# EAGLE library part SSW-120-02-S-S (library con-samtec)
THROUGH-HOLE .025" SQ POST SOCKET Source: Samtec SSW.pdf
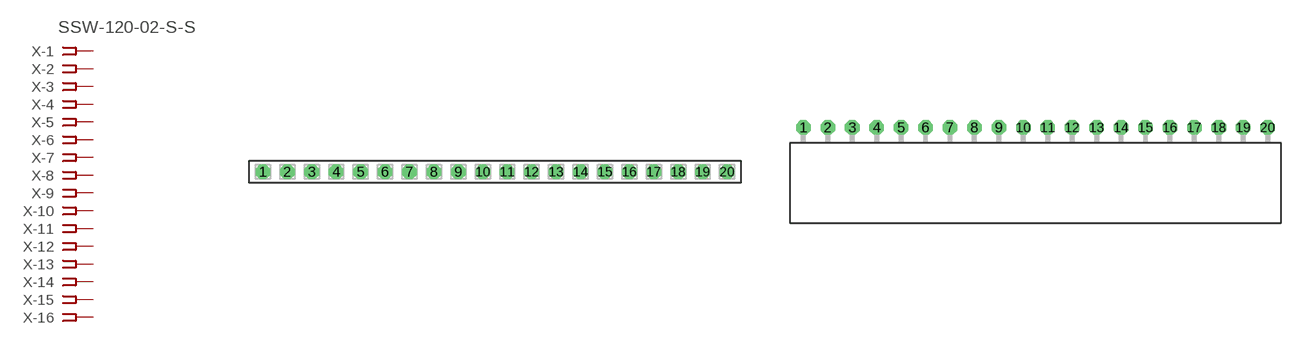
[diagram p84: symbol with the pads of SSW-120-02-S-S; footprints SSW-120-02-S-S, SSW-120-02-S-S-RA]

Designator prefix X; gates -1=FPINV -2=FPIN -3=FPIN -4=FPIN -5=FPIN -6=FPIN -7=FPIN -8=FPIN -9=FPIN -10=FPIN -11=FPIN -12=FPIN -13=FPIN -14=FPIN -15=FPIN -16=FPIN -17=FPIN -18=FPIN -19=FPIN -20=FPIN

## SSW-120-02-S-S (MPN: SSW-120-02-S-S; OC_FARNELL: unknown; OC_NEWARK: 11P9641)  [SSW-120-02-S-S]
1  -1:1  pas
2  -2:1  pas
3  -3:1  pas
4  -4:1  pas
5  -5:1  pas
6  -6:1  pas
7  -7:1  pas
8  -8:1  pas
9  -9:1  pas
10  -10:1  pas
11  -11:1  pas
12  -12:1  pas
13  -13:1  pas
14  -14:1  pas
15  -15:1  pas
16  -16:1  pas
17  -17:1  pas
18  -18:1  pas
19  -19:1  pas
20  -20:1  pas

## SSW-120-02-S-S-RA (MPN: SSW-120-02-S-S-RA; OC_FARNELL: unknown; OC_NEWARK: 11P9642)  [SSW-120-02-S-S-RA]
Pads as for SSW-120-02-S-S

## Footprint SSW-120-02-S-S (pad centres in mm)
THROUGH-HOLE .025" SQ POST SOCKET Source: Samtec SSW.pdf
drill 1 pad 1.5 octagon: 1 -24.13,0; 2 -21.59,0; 3 -19.05,0; 4 -16.51,0; 5 -13.97,0; 6 -11.43,0; 7 -8.89,0; 8 -6.35,0; 9 -3.81,0; 10 -1.27,0; 11 1.27,0; 12 3.81,0; 13 6.35,0; 14 8.89,0; 15 11.43,0; 16 13.97,0; 17 16.51,0; 18 19.05,0; 19 21.59,0; 20 24.13,0

## Footprint SSW-120-02-S-S-RA (pad centres in mm)
THROUGH-HOLE .025" SQ POST SOCKET Source: Samtec SSW.pdf
drill 1 pad 1.5 octagon: 1 -24.13,1.524; 2 -21.59,1.524; 3 -19.05,1.524; 4 -16.51,1.524; 5 -13.97,1.524; 6 -11.43,1.524; 7 -8.89,1.524; 8 -6.35,1.524; 9 -3.81,1.524; 10 -1.27,1.524; 11 1.27,1.524; 12 3.81,1.524; 13 6.35,1.524; 14 8.89,1.524; 15 11.43,1.524; 16 13.97,1.524; 17 16.51,1.524; 18 19.05,1.524; 19 21.59,1.524; 20 24.13,1.524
